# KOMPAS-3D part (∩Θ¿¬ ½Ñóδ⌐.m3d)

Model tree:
1. Эскиз:1
2. Операция выдавливания:1
     Расстояние 1 = 36.6
3. Эскиз:3
4. Вырезать элемент выдавливания:2
     Расстояние 1 = 49.8
5. Фаска:2
     Угол = 45; Длина 1 = 5; Длина 2 = 5
6. Фаска:3
     Угол = 45; Длина 1 = 5; Длина 2 = 5
7. Скругление:1
     Радиус = 1
8. Скругление:2
     Радиус = 1
9. Скругление:3
     Радиус = 1
10. Скругление:4
     Радиус = 2
11. Скругление:5
     Радиус = 2
12. Скругление:6
     Радиус = 2
13. Эскиз:4
14. Вырезать элемент выдавливания:3
     Расстояние 1 = 0.3
15. Эскиз:5
16. Вырезать элемент выдавливания:4
     Расстояние 1 = 0.3
17. Эскиз:6
18. Вырезать элемент выдавливания:6
     Расстояние 1 = 0.3
19. Эскиз:7
20. Вырезать элемент выдавливания:7
     Расстояние 1 = 0.3
21. Эскиз:8
22. Операция выдавливания:2
     Расстояние 1 = 36.6; Расстояние 2 = 1
23. Эскиз:9
24. Операция выдавливания:3
     Расстояние 1 = 2; Расстояние 2 = 1
25. Скругление:7
     Радиус = 1
26. Скругление:8
     Радиус = 0.3
27. Скругление:9
     Радиус = 0.3
28. Скругление:10
     Радиус = 0.3
29. Скругление:11
     Радиус = 0.3
30. Эскиз:10
31. Вырезать элемент выдавливания:8
     Расстояние 1 = 0.3
32. Скругление:12
     Радиус = 0.3
33. Скругление:13
     Радиус = 0.3
34. Скругление:14
     Радиус = 0.3
35. Скругление:15
     Радиус = 0.3
36. Эскиз:11
37. Операция выдавливания:4
     Расстояние 1 = 0.5; Расстояние 2 = 1
38. Эскиз:12
39. Операция выдавливания:5
     Расстояние 1 = 0.3; Расстояние 2 = 1

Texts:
  Сплав АЛ8  ГОСТ 1583-93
